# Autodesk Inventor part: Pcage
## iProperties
Author: vincent molino
Shininess: 41.0
Angle Display Precision: 2
Document Length Units: 11272
Document Angle Units: 11286
Document Time Units: 11279
Document Mass Units: 11290
Document Length Units Precision: 3
Document Angle Units Precision: 2
Compacted: True
PropertySet Name: _Private Model Information
Created: 2002-01
Part Number: Pcage
Document SubType Name: Modeling
Designer: vincent molino
Control State: 0
Master: False
Checked Out: False
PropertySet Name: Design Tracking Control
Density: 0.0
Volumn: 0.0
Area: 0.0
PropertySet Name: Model Information
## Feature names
1. Extrusion1
2. Extrusion2
3. Extrusion3
4. Extrusion4
5. Extrusion5
6. Extrusion6
7. Extrusion7
8. Extrusion8
9. Extrusion9
10. Extrusion10
